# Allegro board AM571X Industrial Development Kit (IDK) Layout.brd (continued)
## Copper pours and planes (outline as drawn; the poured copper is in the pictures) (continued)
VDDR_VREF on L7_PWR2: 92.46,18.83 90.55,20.74 90.55,26.88 88.6,28.83 83.39,28.83 82.55,29.67 82.55,33.61 83.23,34.29 86.28,34.29 95.76,43.77 95.76,65.16 96.77,66.17 96.77,74.04 96.52,74.3 96.52,78.19 96.77,78.44 98.2,78.44 98.3,78.33 98.37,78.33 98.42,78.28 98.42,78.05 98.65,77.83 99.92,77.83 100.03,77.72 100.03,77.42 102.74,74.71 102.74,38.94 103.25,38.44 120.27,38.44 123.19,35.51 123.19,27.72 122.27,26.8 97.5,26.8 96.01,25.31 96.01,19.85 95,18.83
VDDR_VTT on TOP: 107.31,17.27 107.06,17.53 107.06,17.78 106.3,18.54 106.3,27.81 106.55,28.07 108.46,28.07 108.71,27.81 108.71,25.4 109.6,24.51 110.62,24.51 111.89,23.24 111.89,22.61 112.9,21.59 120.78,21.59 121.34,21.03 124.49,21.03 124.97,21.51 124.97,25.15 124.21,25.91 124.21,27.81 124.46,28.07 125.86,28.07 126.36,28.58 126.36,30.48 125.86,30.99 124.84,30.99 124.21,31.62 124.21,32.13 124.46,32.38 127.38,32.38 129.03,30.73 129.03,26.16 128.14,25.27 128.14,20.07 126.11,18.03 118.39,18.03 115.85,20.57 111.51,20.57 109.98,22.1 108.33,22.1 107.82,21.59 107.82,17.53 107.57,17.27
VDDR_VTT on BOTTOM: 107.31,23.62 108.46,22.48 110.62,22.48 111.38,21.72 111.38,19.3 111.76,18.92 127.13,18.92 128.35,20.14 128.35,29.69 128.07,29.97 124.41,29.97 124.21,29.77 124.21,22.48 123.32,21.59 114.05,21.59 113.54,22.1 113.54,22.61 108.71,27.43 108.71,28.19 108.58,28.32 108.58,30.61 108.46,30.73 107.57,30.73 107.31,30.48
VDDS_DDR on TOP (solid shape): 150.88,120.78 150.88,119.46 151.89,118.45 151.89,117.22 151.38,116.71 148.72,116.71 148.21,117.22 148.21,120.52 148.59,120.9 150.75,120.9
VDDS_DDR on TOP: 61.09,75.01 64.01,75.01 64.14,74.88 64.14,72.6 63.63,72.09 60.96,72.09 60.58,72.47 60.58,74.5
VDDS_DDR on TOP: 108.71,17.06 109.09,17.44 109.09,17.95 109.73,18.59 109.73,20.11 109.98,20.37 109.98,21.46 109.73,21.72 108.46,21.72 108.2,21.46 108.2,17.06
VDDS_DDR on BOTTOM: 83.95,36.32 85.85,36.32 86.11,36.07 86.11,35.69 85.85,35.43 83.95,35.43 83.69,35.69 83.69,36.07
VDDS_DDR on BOTTOM: 109.86,18.54 110.11,18.8 110.11,21.46 109.73,21.84 108.58,21.84 108.2,21.46 108.2,18.67 108.33,18.54
VDDS_DDR on BOTTOM: 86.74,33.43 87.1,33.78 87.38,33.78 87.63,33.53 87.63,32.26 87.25,31.88 84.33,31.88 83.69,32.51 83.69,33.3 83.82,33.43
VDDS_DDR on L6_PWR1: 151.26,119.21 144.4,119.21 141.99,116.79 133.22,116.79 132.33,115.91 132.33,114.76 126.24,108.67 126.24,105.49 125.09,104.35 121.41,104.35 120.27,103.21 120.27,89.74 120.35,89.67 120.35,77.42 119.93,77 119.93,48.63 113.66,42.37 67.18,42.37 65.15,44.4 65.15,73.84 63.91,75.09 51,75.09 49.78,73.87 49.78,26.37 51.64,24.52 65.46,24.52 71.58,18.39 82.55,18.39 84.86,16.08 97.66,16.08 99.95,18.37 111.76,18.37 112.78,17.35 113.41,17.35 114.43,18.37 164.21,18.37 168.4,22.56 168.4,86.36 166.73,88.03 143.07,88.03 140.59,90.51 140.59,101.94 152.02,113.37 152.02,118.45
(no net) on TOP: 127.06,136.13 129.96,136.13 130.51,135.58 130.51,133.91 130.35,133.74 126.88,133.74 126.67,133.96 126.67,135.74
(no net) on TOP: 140.21,120.73 141.22,120.73 141.61,120.35 141.61,118.95 141.48,118.83 140.59,118.83 139.95,119.46 139.95,120.48
(no net) on TOP: 145.03,128.61 145.03,130.13 147.7,132.8 147.7,134.19 147.83,134.32 150.88,134.32 151.13,134.07 151.13,132.03 149.61,130.51 149.1,130.51 147.96,129.37 147.96,129.11 146.49,127.65 144.71,127.65 144.65,127.72 144.65,128.25 144.65,128.26 144.65,128.31 144.76,128.41 144.84,128.41
(no net) on TOP: 138.59,131.47 138.21,131.1 138.05,131.1 138.05,131.25 137.94,131.36 137.94,133.32 138.18,133.56 138.43,133.56 138.59,133.4
(no net) on TOP: 143.26,113.62 145.59,113.62 145.8,113.41 145.8,108.46 146.56,107.7 146.56,105.16 145.8,104.39 144.15,104.39 143,105.54 143,113.37
(no net) on TOP: 151.38,116.71 148.72,116.71 148.21,117.22 148.21,120.52 148.59,120.9 150.75,120.9 150.88,120.78 150.88,119.46 151.89,118.45 151.89,117.22
(no net) on TOP: 133.86,113.62 136.53,113.62 136.91,113.24 136.91,110.83 136.65,110.57 133.86,110.57 133.48,110.95 133.48,113.24
(no net) on TOP: 133.6,116.42 133.57,116.4 133.57,115.43 133.99,115.02 136.91,115.02 138.03,116.14 138.03,120.37 138.05,120.39 138.05,120.6 137.82,120.83 137.67,120.68 137.67,120.6 137.54,120.48 137.54,119.97 136.65,119.08 134.11,119.08 133.6,118.56
(no net) on TOP: 139.32,119.97 139.45,119.97 141.1,118.32 141.86,118.32 142.11,118.06 142.11,115.52 141.73,115.14 138.68,115.14 138.43,115.4 138.43,118.83 139.19,119.59 139.19,119.84
(no net) on TOP: 127.47,132.59 130.3,132.59 130.3,132.54 133.99,128.86 134.9,128.86 134.87,128.84 136.22,128.84 136.33,128.73 136.33,128.22 136.23,128.13 136.11,128.13 135.98,128.26 135.72,128.26 135.67,128.21 135.59,128.13 134.24,128.13 134.04,128.34 132.22,128.34 130.18,130.38 127.25,130.38 127.12,130.51 127.12,132.24
(no net) on TOP: 127.67,127.21 129.92,127.21 130.68,127.97 133.22,127.97 133.6,127.59 133.6,126.18 133.22,125.8 132.06,125.8 130.79,124.53 127.24,124.53 127.19,124.58 127.19,126.73
(no net) on TOP: 138.81,113.62 141.1,113.62 142.09,112.63 142.09,111.05 141.61,110.57 138.56,110.57 138.18,110.95 138.18,112.98
(no net) on TOP: 134.14,141.3 138.98,141.3 139.55,140.73 139.55,136.09 137.54,134.08 137.54,131.11 136.94,130.51 136.78,130.51 136.53,130.76 135,130.76 134.75,130.51 134.36,130.51 134.04,130.82 134.04,135.53 133.55,136.02 133.55,137.02 132.89,137.68 132.89,140.06
(no net) on TOP: 133.22,125.4 132.06,125.4 130.73,124.08 127.32,124.08 127.32,124.07 127.27,124.07 127.08,123.89 127.08,121.66 127.38,121.37 131.95,121.37 133.27,122.68 133.27,125.36
(no net) on TOP: 138.83,133.32 138.94,133.43 138.94,133.81 139.07,133.94 139.32,133.94 139.47,133.78 139.47,131.27 139.32,131.12 139.32,130.31 139.24,130.23 139.04,130.23 138.83,130.44
(no net) on TOP: 150.88,124.92 150.37,125.43 145.92,125.43 145.29,124.8 145.29,124.03 145.92,123.4 147.57,123.4 149.1,121.87 150.5,121.87 150.88,122.26
(no net) on TOP: 142.49,120.1 143,119.59 144.78,119.59 146.69,117.68 146.69,115.65 146.3,115.27 143.13,115.27 142.75,115.65 142.75,118.06 141.99,118.83 141.99,119.97 142.11,120.1
(no net) on TOP: 145.03,127.21 146.69,127.21 148.34,128.86 148.34,129.11 148.59,129.37 150.88,129.37 151.26,128.99 151.26,126.07 151,125.81 145.16,125.81 144.7,126.28 144.7,126.87
(no net) on TOP: 144.78,130.89 144.78,131.78 145.03,132.03 145.03,134.45 145.29,134.7 146.69,134.7 146.94,134.45 146.94,132.67 145.03,130.76 144.91,130.76
(no net) on TOP: 137.29,121.24 137.29,120.1 136.65,119.46 135.26,119.46 135.13,119.59 135.13,119.97 136.02,120.86 136.02,121.11 136.27,121.37 137.16,121.37
(no net) on TOP: 141.35,135.84 141.99,135.84 142.11,135.72 142.11,133.18 141.61,132.67 140.84,132.67 140.21,133.3 140.21,134.7
(no net) on TOP: 149.53,88.14 157.35,88.14 159.82,85.67 159.82,83.95 159.44,83.57 159.18,83.57 157.4,81.79 156.26,81.79 154.86,80.4 149.91,80.4 148.89,81.41 148.89,87.51
(no net) on TOP: 151.77,126.95 151.77,134.07 152.27,134.57 153.54,134.57 154.56,133.56 154.56,127.46 153.92,126.83 151.89,126.83
(no net) on BOTTOM: 142.37,134.83 146.43,134.83 146.56,134.96 146.56,136.61 146.3,136.86 142.37,136.86 142.11,136.61 142.11,135.08
(no net) on BOTTOM: 39.5,92.84 39.5,98.17 39.75,98.42 41.02,98.42 42.29,97.16 43.69,97.16 44.45,97.92 48.39,97.92 49.28,97.03 49.28,95.63 48.26,94.61 43.05,94.61 41.4,92.96 41.4,91.57 40.64,90.8 38.48,90.8 38.23,91.06 38.23,91.57
(no net) on BOTTOM: 117.73,128.91 113.03,128.91 112.78,129.16 112.78,130.3 113.03,130.56 119.38,130.56 121.16,128.78 121.16,124.97 120.9,124.71 120.27,124.71 120.02,124.97 120.02,127.13 119.51,127.64 119,127.64
(no net) on BOTTOM: 137.03,121.62 137.03,120.1 136.78,119.84 136.78,117.94 137.03,117.68 142.49,117.68 143,118.19 143,121.24 142.88,121.37 138.68,121.37 138.18,121.87 137.29,121.87
(no net) on BOTTOM: 145.01,129.65 146.63,129.65 147.07,129.21 147.07,128.27 146.79,128 145.39,128 144.88,128.5 144.88,129.52
(no net) on BOTTOM: 148.34,134.07 150.24,134.07 150.5,133.81 150.5,127.46 150.24,127.21 148.34,127.21 148.08,127.46 148.08,133.81
(no net) on BOTTOM: 127.13,134.07 127.13,135.84 127.51,136.23 130.18,136.23 130.68,135.72 130.68,134.19 130.35,133.86 127.33,133.86
(no net) on BOTTOM: 139.34,125.7 139.57,125.93 140.72,125.93 140.97,125.68 140.97,124.41 140.84,124.29 138.18,124.29 137.92,124.03 137.92,123.14 136.27,123.14 136.14,123.27 136.14,125.3 136.54,125.7
(no net) on BOTTOM: 36.2,93.09 38.1,93.09 38.23,92.96 38.23,92.33 37.97,92.08 37.97,91.06 37.72,90.8 36.96,90.8 34.42,93.34 34.42,96.27 34.67,96.52 35.18,96.52 35.31,96.39 35.31,93.98
(no net) on BOTTOM: 154.74,106.9 154.23,106.9 153.32,107.81 151.48,107.81 151,108.29 149.48,108.29 149.23,108.03 149.23,106.51 149.47,106.27 154.74,106.27
(no net) on BOTTOM: 146.39,125.81 148.84,125.81 149.1,125.56 149.1,122.89 147.7,121.49 147.7,119.84 147.57,119.72 146.6,119.72 144.78,121.54 144.78,122.05 145.03,122.3 145.03,124.46
(no net) on BOTTOM: 151.64,133.81 152.4,134.57 154.18,134.57 154.69,134.07 154.69,126.95 154.31,126.57 152.02,126.57 151.64,126.95
(no net) on BOTTOM: 159.05,112.87 159.05,110.35 155.99,107.28 155.63,107.28 155.63,107.37 155.91,107.65 155.91,108.69 155.63,108.97 155.63,112.87 156.13,113.38 158.55,113.38
(no net) on BOTTOM: 34.04,96.9 37.34,96.9 38.23,97.79 38.23,98.42 37.97,98.68 34.04,98.68 33.91,98.55 33.91,97.03
(no net) on BOTTOM: 133.22,127.34 133.22,130.38 132.84,130.76 131.44,130.76 131.19,131.02 131.19,132.54 131.44,132.8 135.26,132.8 135.76,132.29 135.76,130.64 135.13,130 135.13,128.86 135.64,128.35 135.76,128.35 136.14,127.97 136.14,126.83 135.64,126.32 134.87,126.32 134.11,125.56 133.1,125.56 132.97,125.68 132.97,127.08
(no net) on BOTTOM: 158.8,83.13 164.01,83.13 164.39,82.75 164.39,81.48 164.13,81.22 159.18,81.22 158.55,81.86 158.55,82.87
(no net) on BOTTOM: 139.32,134.96 138.05,134.96 137.16,135.84 137.16,136.73 137.41,136.99 139.07,136.99 139.45,136.61 139.45,135.08
(no net) on BOTTOM: 153.45,105.9 150.16,105.9 149.91,105.65 149.91,103.58 150.11,103.38 153.1,103.38 153.72,104 153.72,105.63
(no net) on BOTTOM: 130.99,130.05 132.13,130.05 132.64,129.54 132.64,128.38 132.33,128.07 131.17,128.07 130.71,128.53 130.71,129.77
(no net) on BOTTOM: 141.35,127.21 143.64,127.21 143.76,127.08 143.76,126.07 143.64,125.94 141.35,125.94 141.1,126.19 141.1,126.95
(no net) on BOTTOM: 117.47,125.73 117.47,127.51 117.6,127.64 118.24,127.64 118.49,127.38 119.51,127.38 119.76,127.13 119.76,124.21 118.49,122.94 114.43,122.94 114.05,123.32 114.05,124.59 114.17,124.71 116.46,124.71
(no net) on BOTTOM: 145.36,132.11 144.68,131.42 141.27,131.42 141.1,131.6 141.1,132.16 141.73,132.8 141.73,133.86 142.06,134.19 145.29,134.19 145.36,134.12
(no net) on BOTTOM: 4.32,47.2 5.03,46.49 5.03,43.34 4.8,43.11 3.2,43.11 2.54,43.77 1.43,43.77 1.43,46.97 1.65,47.2
(no net) on BOTTOM: 4.75,39.12 4.95,38.92 4.95,35.41 4.55,35.01 2.03,35.01 1.3,35.74 1.3,38.08 2.16,38.08 3.2,39.12
(no net) on BOTTOM: 35.81,96.52 38.23,96.52 38.35,96.39 38.35,94.36 38.1,94.11 35.81,94.11 35.64,94.28 35.64,96.34
(no net) on BOTTOM: 155.02,107.01 155.02,107.25 154.67,107.6 154.67,108.49 153.47,109.7 153.47,112.62 152.83,113.25 151.43,113.25 151.05,112.87 151.05,109.95 152.83,108.17 153.85,108.17 155.01,107.01
(no net) on BOTTOM: 113.66,123.7 113.66,126.75 112.14,128.27 112.14,131.7 111.76,132.08 109.98,132.08 109.73,131.83 109.73,128.14 111.89,125.98 111.89,123.7 112.27,123.32 113.28,123.32
(no net) on BOTTOM: 133.48,113.37 136.78,113.37 137.03,113.11 137.03,110.83 136.78,110.57 133.99,110.57 133.35,111.21 133.35,113.24
(no net) on BOTTOM: 158.93,81.16 164.13,81.16 164.52,80.78 164.52,79.51 164.21,79.2 159.36,79.2 158.67,79.89 158.67,80.9
(no net) on BOTTOM: 130.89,126.78 132.38,126.78 132.46,126.7 132.46,125.05 132.21,124.8 131.32,124.8 130.68,125.43 130.68,126.57
(no net) on BOTTOM: 127.38,122.51 127.38,126.32 127.51,126.45 130.05,126.45 130.56,125.94 130.56,122.64 130.3,122.38 127.51,122.38
(no net) on BOTTOM: 167.13,43.39 167.13,45.8 167.39,46.06 168.02,46.06 168.34,45.74 168.34,44.98 168.53,44.79 168.53,43.52 168.28,43.26 167.26,43.26
(no net) on BOTTOM: 125.55,115.17 125.3,115.42 125.3,117.86 125.73,118.29 129.01,118.29 129.29,118.01 129.29,115.47 128.98,115.17
(no net) on BOTTOM: 173.06,94.19 170.39,94.19 170.13,93.93 170.13,91.14 170.52,90.76 174.45,90.76 174.83,91.14 174.83,92.54 174.71,92.66 173.82,92.66 173.31,93.17 173.31,93.93
(no net) on BOTTOM: 127.25,130 130.3,130 130.56,129.75 130.56,127.97 130.3,127.72 127.51,127.72 127.13,128.1 127.13,129.88
(no net) on BOTTOM: 114.05,125.22 114.05,127.64 114.17,127.76 116.2,127.76 116.46,127.51 116.46,125.22 116.28,125.04 114.22,125.04
(no net) on BOTTOM: 127.25,121.09 130.3,121.09 130.56,120.83 130.56,119.06 130.3,118.8 127.51,118.8 127.13,119.18 127.13,120.96
(no net) on BOTTOM: 133.22,125.3 135,125.3 135.26,125.05 135.26,123.02 135.13,122.89 132.08,122.89 131.93,123.04 131.93,123.37 132.23,123.68 132.23,124.31
(no net) on BOTTOM: 141.1,129.11 143.74,129.11 144.91,127.94 144.91,127.53 144.7,127.32 144.03,127.32 143.64,127.72 141.35,127.72 140.97,127.34 140.97,126.45 140.87,126.35 139.8,126.35 139.7,126.45 139.7,127.72
(no net) on BOTTOM: 131.32,135.59 131.32,133.56 131.57,133.3 135.76,133.3 136.14,133.69 136.14,135.97 135.89,136.23 131.95,136.23
(no net) on BOTTOM: 138.94,133.18 138.94,131.65 139.07,131.53 139.95,131.53 140.21,131.78 140.21,134.19 139.83,134.57 138.56,134.57 138.3,134.32 138.3,133.81
(no net) on BOTTOM: 127.38,132.16 130.56,132.16 130.81,131.91 130.81,131.27 130.43,130.89 127.38,130.89 127.25,131.02 127.25,132.03
(no net) on L3_SIG1: 27.2,83.16 34.11,83.16 35.64,81.64 35.64,78.47 34.92,77.75 24.92,77.75 24.21,78.47 24.21,80.17
(no net) on L3_SIG1: 26.54,100.54 27.86,100.54 30.91,97.49 33.27,97.49 33.91,96.86 33.91,96.22 33.27,95.59 24.54,95.59 24.21,95.92 24.21,98.2
(no net) on L3_SIG1: 26.03,58.76 32.29,58.76 35.64,55.41 35.64,53.88 35.26,53.5 34.37,53.5 33.6,54.26 24.59,54.26 24.21,54.64 24.21,56.93
(no net) on L10_SIG4: 36.96,98.3 37.59,97.66 37.59,97.03 37.08,96.52 34.29,96.52 33.66,97.16 33.66,97.79 34.16,98.3
AM57XX_USB1_DRVVBUS on L9_SIG3: 93.7,87.33 94.74,87.33 95.76,86.31 95.76,84.27 94.82,83.33 91.56,83.33 86.5,88.39 86.5,88.4 85.72,89.18 85.72,90.63 86.02,90.93 87.41,90.93 88.55,89.8 88.55,87.97 90.48,86.03 92.41,86.03 92.41,86.04
BKLT_L on TOP: 70.86,144.25 70.36,144.75 70.36,146.41 70.74,146.79 80.13,146.79 80.64,146.28 80.64,144.63 80.26,144.25
BKLT_L on BOTTOM: 73.13,146.61 73.13,145.6 72.24,145.6 71.48,144.84 70.59,144.84 70.36,145.07 70.36,146.38 70.59,146.61
BKLT_SW on TOP: 70.74,140.94 70.36,141.33 70.36,143.48 70.74,143.87 80.26,143.87 80.64,143.48 80.64,141.58 80.01,140.94
BKLT_SW on BOTTOM: 73.15,143.57 73.15,142.7 72.27,142.7 71.86,142.3 70.34,142.3 70.09,142.55 70.09,143.31 70.34,143.57
ETH1_LDO_O on TOP: 64.64,111.08 65.53,111.08 65.79,110.83 65.79,107.78 65.66,107.65 64.52,107.65 64.39,107.78 64.39,110.83
FTDI_VPHY on BOTTOM (solid shape): 164.39,82.75 164.39,81.57 164.36,81.52 164.3,81.53 164.29,81.54 160.33,81.54 160.32,81.57 159.94,81.82 159.57,81.57 159.56,81.54 158.86,81.54 158.55,81.86 158.55,82.87 158.8,83.13 164.01,83.13
FTDI_VPLL on BOTTOM (solid shape): 159.63,81.16 159.94,81 160.26,81.16 164.13,81.16 164.52,80.78 164.52,79.51 164.21,79.2 161.34,79.2 161.25,79.31 161.13,79.38 161.13,79.51 160.62,79.51 160.62,79.38 160.5,79.31 160.41,79.2 159.36,79.2 158.67,79.89 158.67,80.9 158.93,81.16
VADD33_PRU1ETH0 on BOTTOM: 21.97,121.87 21.97,123.14 22.48,123.65 23.37,123.65 23.62,123.4 23.62,123.02 23.37,122.76 23.11,122.76 22.23,121.87
VADD33_PRU1ETH1 on TOP: 26.11,100.54 26.54,100.54 27.03,100.06 27.03,98.63 26.8,98.4 26.39,98.4 26.16,98.63 26.16,99.78 25.88,100.06 25.88,100.31
VADD33_PRU1ETH1 on BOTTOM: 26.37,101.43 29.79,101.43 29.92,101.3 29.92,100.16 29.67,99.9 27.53,99.9 27.03,99.4 27.03,98.63 26.77,98.38 26.37,98.38 25.98,98.76 25.98,101.05
VADD33_PRU2ETH0 on TOP: 26.06,82.78 26.54,82.78 26.97,82.35 26.97,80.9 26.8,80.73 26.31,80.73 25.98,81.06 25.98,82.4 26.06,82.48
VADD33_PRU2ETH0 on BOTTOM: 26.37,83.73 29.79,83.73 29.92,83.6 29.92,82.46 29.67,82.2 29.03,82.2 27.51,80.68 26.37,80.68 25.98,81.06 25.98,83.35
VADD33_PRU2ETH1 on TOP: 26.37,57.41 27.51,57.41 27.74,57.18 27.74,56.8 27.53,56.6 27.1,56.6 26.97,56.47 26.97,56.11 26.72,55.86 26.31,55.86 26.16,56.01 26.16,57.18 26.37,57.38
VADD33_PRU2ETH1 on BOTTOM: 26.37,58.96 29.79,58.96 29.92,58.84 29.92,57.69 29.67,57.44 29.03,57.44 29,57.41 28.4,57.41 27.56,56.57 27.3,56.57 27,56.27 27,55.91 26.37,55.91 25.98,56.3 25.98,58.58
VAM572X_DDR1 on TOP: 95.77,74.26 96.51,74.26 96.65,74.12 96.65,72.69 96.51,72.56 95.69,72.56 95.58,72.67 95.58,74.07
VAM572X_DDR1 on TOP: 67.06,72.47 69.22,72.47 69.72,71.96 69.72,71.2 69.22,70.69 67.06,70.69 66.55,71.2 66.55,71.96
VAM572X_DDR1 on TOP: 95.94,76.71 97.18,76.71 97.33,76.56 97.33,75.26 97.08,75.01 95,75.01 94.82,75.18 94.82,75.59
VAM572X_DDR1 on TOP: 100.6,74.28 101.38,74.28 101.57,74.09 101.57,72.75 101.41,72.58 100.52,72.58 100.33,72.77 100.33,74.02
VAM572X_DDR1 on TOP: 61.09,78.69 63.63,78.69 64.14,78.19 64.14,75.9 64.01,75.77 61.09,75.77 60.71,76.15 60.71,78.31
VAM572X_DDR1 on BOTTOM: 66.29,72.47 71.37,72.47 72.01,71.84 72.01,66.88 71.5,66.38 67.18,66.38 65.79,67.77 65.79,71.96
VAM572X_DDR1 on BOTTOM: 93.85,75.92 95.66,75.92 96.14,75.44 96.14,73.79 97.92,72.01 97.92,70.74 97.79,70.61 95.89,70.61 95.76,70.74 95.76,71.58 95.59,71.75 94.61,71.75 94.36,71.5 94.36,70.23 94.16,70.03 91.82,70.03 90.17,71.68 90.17,72.26 90.53,72.62 91.16,72.62 91.54,72.24 91.54,71.5 91.82,71.22 92.18,71.22 93.73,72.77 93.73,75.79
VAM572X_DDR1 on L3_SIG1: 95.38,76.28 96.65,76.28 96.85,76.07 96.85,75.64 96.65,75.44 96.39,75.44 96.01,75.06 94.54,75.06 94.54,75.44
VAM572X_DDR1 on L3_SIG1: 101.02,73.55 101.02,72.36 100.72,72.07 100.29,72.07 99.92,72.44 99.92,73.71 100.13,73.91 100.65,73.91
VAM572X_DDR1 on L6_PWR1: 67.82,42.63 65.79,44.66 65.79,74.12 64.14,75.77 60.2,75.77 59.44,76.54 59.44,82.25 60.83,83.65 94.23,83.65 94.46,83.42 100.84,83.42 101.09,83.16 101.09,79.5 100.18,78.59 100.18,76.73 100.71,76.2 116.08,76.2 117.22,77.34 117.22,101.22 120.78,104.77 125.35,104.77 126.24,105.66 126.24,108.97 132.46,115.19 132.46,116.2 133.73,117.47 141.99,117.47 143.89,119.38 143.89,120.4 144.15,120.65 145.92,120.65 146.3,120.27 146.3,119 141.99,114.68 135.76,114.68 129.16,108.08 129.16,104.65 126.11,101.6 123.95,101.6 123.19,100.84 123.19,52.28 113.54,42.63
VAM572X_DDR1 on L10_SIG4: 96.52,71.46 96.14,71.07 95.76,71.07 95.63,71.2 95.63,71.46 94.61,72.47 94.61,73.99 93.8,74.8 93.8,75.16 93.93,75.29 94.46,75.29 95.28,76.1 95.99,76.1 95.99,75.64 96.14,75.49 96.14,75.23 95.96,75.06 95.96,74.85 96.52,74.3
VCAN1 on TOP: 165.96,29.6 167.94,29.6 168.33,29.21 168.33,26.04 165.56,23.27 157.53,23.27 155.63,21.37 155.63,13.92 154.53,12.83 151.54,12.83 151,13.37 148.54,13.37 148.08,13.82 148.08,19.89 155.07,26.88 164.54,26.88 165.35,27.69 165.35,28.99
VETH0_AVDDH on BOTTOM: 48.13,116.92 48.89,116.16 48.89,113.75 48.51,113.37 47.5,113.37 46.86,114 46.86,117.94 46.48,118.32 46.48,123.91 46.74,124.16 47.88,124.16 48.13,123.91
VETH0_AVDDH on L4_SIG2: 30.48,127.34 44.96,127.34 47.75,124.54 47.75,122.51 46.61,121.37 40.26,121.37 37.08,124.54 30.61,124.54 29.97,125.18 29.97,126.83
VETH0_AVDDL on BOTTOM: 43.69,123.65 43.69,124.8 43.43,125.05 38.84,125.05 38.33,125.56 33.66,125.56 33.15,125.05 33.15,124.41 33.66,123.91 37.87,123.91 38.25,123.53 43.56,123.53
VETH0_AVDDL_PLL on BOTTOM: 38.94,123.02 43.05,123.02 43.81,122.26 43.81,121.24 43.56,120.99 38.99,120.99 38.73,121.24 38.73,122.81
VETH0_AVDDL_PMOS on BOTTOM: 43.31,109.17 43.31,110.32 44.7,111.71 44.7,117.56 44.2,118.06 44.2,125.05 43.81,125.43 43.81,126.95 44.32,127.46 46.1,127.46 46.48,127.08 46.48,125.56 45.97,125.05 45.97,118.06 46.61,117.43 46.61,112.22 47.62,111.21 47.62,109.05 47.24,108.67 43.81,108.67
VETH0_DVDDH on BOTTOM: 28.45,118.19 29.08,118.19 30.23,117.05 30.43,117.05 30.86,116.62 30.86,116.16 30.35,115.65 28.45,115.65 27.69,116.41 27.69,117.43
VETH0_DVDDH on L4_SIG2: 29.34,122.89 29.97,122.89 32.38,120.48 42.42,120.48 43.18,119.72 43.18,111.33 43.14,111.29 43.14,108.6 42.07,107.52 38.32,107.52 38.14,107.7 38.14,109.66 39.88,111.4 39.88,112.86 39.24,113.49 30.86,113.49 28.45,115.91 27.43,115.91 27.05,116.29 27.05,120.6
VETH0_DVDDL on BOTTOM: 43.56,119.59 43.81,119.33 43.81,118.45 43.56,118.19 42.55,118.19 41.27,116.92 38.61,116.92 37.41,115.73 32.21,115.73 29.59,118.34 29.59,122.51 30.48,123.4 31.62,123.4 32.77,122.26 32.77,121.49 34.67,119.59
VETH1_AVDDH on TOP: 72.9,106.25 72.39,105.75 69.34,105.75 68.96,106.13 68.96,110.19 70.61,111.84 70.61,116.67 69.47,117.81 69.47,127.59 68.58,128.48 64.64,128.48 64.01,129.11 64.01,130.51 64.26,130.76 70.48,130.76 72.9,128.35
VETH1_AVDDH on BOTTOM: 50.67,127.08 52.45,127.08 53.09,126.45 58.06,126.45 62.38,130.76 66.67,130.76 67.06,130.38 67.06,128.86 66.67,128.48 62.03,128.48 60.2,126.65 60.2,125.53 60.1,125.43 59.21,125.43 59.08,125.56 54.81,125.56 53.8,124.54 50.67,124.54 50.29,124.92 50.29,126.7
VETH1_AVDDL on TOP: 65.53,123.27 65.28,123.02 64.14,123.02 63.63,123.53 63.63,124.8 63.88,125.05 65.41,125.05 65.53,124.92
VETH1_AVDDL on BOTTOM: 65.66,124.54 65.15,125.05 59.05,125.05 58.55,125.56 55.37,125.56 54.86,125.05 54.86,124.41 55.68,123.6 64.31,123.6 64.9,123.02 65.41,123.02 65.66,123.27
VETH1_AVDDL_PLL on TOP: 64.39,122.64 65.28,122.64 65.53,122.38 65.53,120.86 65.28,120.6 64.14,120.6 63.88,120.86 63.88,121.24 64.14,121.49 64.14,122.38
VETH1_AVDDL_PLL on BOTTOM: 60.71,123.27 64.52,123.27 65.53,122.26 65.53,120.99 65.28,120.73 64.01,120.73 63.75,120.99 60.58,120.99 60.32,121.24 60.32,122.89
VETH1_AVDDL_PMOS on TOP: 65.91,111.46 65.91,128.22 66.42,128.73 67.69,128.73 68.77,127.65 68.77,116.98 69.47,116.29 69.47,112.6 68.2,111.33 68.2,107.78 67.82,107.4 66.8,107.4 66.55,107.65 66.55,110.83
VETH1_DVDDH on BOTTOM: 50.04,115.02 51.31,115.02 51.43,114.89 51.43,112.6 51.31,112.48 49.4,112.48 49.15,112.73 49.15,114.51 49.53,114.89 49.91,114.89
VETH1_DVDDH on L4_SIG2: 52.07,122.89 61.59,122.89 64.26,120.22 64.26,111.08 61.93,108.74 49.76,108.74 48.64,109.86 48.64,119.59 47.88,120.35 47.88,121.62 49.78,123.53 51.43,123.53
VETH1_DVDDL on BOTTOM: 58.55,118.19 59.44,118.19 60.83,119.59 64.01,119.59 64.01,119.84 64.52,120.35 65.28,120.35 65.53,120.1 65.53,117.81 64.64,116.92 60.32,116.92 58.93,115.52 51.43,115.52 51.31,115.65 51.31,122.51 52.2,123.4 53.34,123.4 54.48,122.26 54.48,119.97 55.5,118.95 57.78,118.95
VLDO2_OUT on TOP (solid shape): 139.47,133.78 139.47,131.67 139.46,131.64 139.43,131.62 139.13,131.4 139.23,131.04 139.24,131.03 139.24,130.96 139.23,130.95 139.14,130.74 139.23,130.53 139.26,130.45 139.23,130.38 139.06,130.21 138.83,130.44 138.83,130.5 138.85,130.51 138.95,130.75 138.83,130.98 138.83,131.18 138.97,131.32 138.97,133.56 138.94,133.59 138.94,133.81 139.07,133.94 139.32,133.94
VLDO2_OUT on BOTTOM (solid shape): 140.02,134.38 140.02,134.36 140.09,134.18 140.21,134.02 140.21,131.78 139.95,131.53 139.07,131.53 138.94,131.65 138.94,133.18 138.88,133.24 138.87,133.26 138.7,133.64 138.3,133.8 138.3,134.32 138.56,134.57 139.07,134.57 139.83,134.57
VLED+ on BOTTOM: 73.41,136.86 70.36,136.86 69.98,137.24 69.98,138.64 70.23,138.89 70.23,141.69 70.48,141.94 72.36,141.94 73.28,142.32 73.41,142.45 73.66,142.45 73.79,142.32 73.79,137.24
VLED+ on L9_SIG3: 71.25,141.81 75.36,141.81 82.55,134.62 82.55,128.48 81.91,127.84 80.01,127.84 70.61,137.24 70.61,141.18
VLED- on BOTTOM: 76.07,146.64 76.58,147.15 81.41,147.15 82.04,146.51 82.04,145.12 81.61,144.68 78.18,144.68 77.5,145.37 75.79,145.37 75.54,145.62 75.06,145.62 74.93,145.75 74.93,146.51 75.06,146.64
VLED- on BOTTOM: 82.42,124.8 81.79,125.43 81.79,127.08 82.04,127.34 82.68,127.34 82.8,127.46 84.96,127.46 85.09,127.34 85.09,125.05 84.84,124.8
VLED- on L9_SIG3: 77.85,146.51 78.87,147.53 81.03,147.53 88.77,139.78 88.77,126.45 86.36,124.03 81.91,124.03 81.28,124.67 81.28,126.7 81.66,127.08 81.91,127.08 83.31,128.48 83.31,135.26 77.85,140.72
VMAIN on TOP (solid shape): 141.54,120.41 141.54,118.95 141.54,118.89 141.48,118.83 140.59,118.83 140.01,119.4 140.02,119.46 140.02,120.54 140.21,120.73 141.22,120.73
VMAIN on TOP (solid shape): 137.28,121.24 137.28,121.18 137.27,121.14 137.27,120.08 136.65,119.46 135.26,119.46 135.13,119.59 135.13,119.97 136.02,120.86 136.02,121.11 136.27,121.37 137.16,121.37
VMAIN on BOTTOM (solid shape): 147.07,129.21 147.07,128.27 147,128.21 145.18,128.21 144.88,128.51 144.88,129.52 145.01,129.65 146.63,129.65
VMAIN on BOTTOM (solid shape): 151.48,107.81 153.32,107.81 154.23,106.9 154.74,106.9 154.74,106.27 153.34,106.27 153.34,106.27 152.83,106.27 152.83,106.27 149.47,106.27 149.23,106.51 149.23,108.03 149.48,108.29 151,108.29
VMAIN on BOTTOM (solid shape): 145.36,134.12 145.36,132.11 144.68,131.42 141.84,131.42 141.73,131.44 141.63,131.42 141.27,131.42 141.1,131.6 141.1,132.16 141.73,132.8 141.73,133.86 142.06,134.19 145.29,134.19
VMAIN on BOTTOM (solid shape): 135.76,132.29 135.76,130.64 135.13,130 135.13,128.86 135.64,128.35 135.76,128.35 136.14,127.97 136.14,126.84 136.1,126.81 136.07,126.78 135.61,126.32 134.87,126.32 134.42,125.87 132.97,125.87 132.97,127.08 133.22,127.34 133.22,130.38 132.84,130.76 131.44,130.76 131.19,131.02 131.19,132.54 131.44,132.8 135.26,132.8
VMAIN on BOTTOM (solid shape): 149.1,125.56 149.1,122.89 147.7,121.49 147.7,119.84 147.57,119.72 146.6,119.72 146.2,120.12 146.2,120.14 146.08,120.43 145.79,120.55 145.77,120.55 144.78,121.54 144.78,122.05 145.03,122.3 145.03,123.18 145.08,123.31 145.1,123.44 145.1,124.52 145.48,124.9 145.67,124.9 146.12,125.12 146.22,125.61 146.22,125.64 146.39,125.81 148.84,125.81
VMAIN on BOTTOM (solid shape): 138.68,121.37 139.78,121.37 139.85,121.34 139.88,121.27 140.21,120.95 140.54,121.27 140.57,121.34 140.64,121.37 141.56,121.37 141.57,121.36 141.73,121.33 141.9,121.36 141.91,121.37 142.57,121.37 142.67,121.34 142.76,121.33 142.91,121.33 143,121.24 143,118.19 142.88,118.07 142.86,118.07 142.65,118.01 142.49,117.87 142.45,117.82 142.39,117.88 141.87,118.03 141.45,117.68 137.03,117.68 136.78,117.94 136.78,119.84 137.03,120.1 137.03,121.62 137.29,121.87 138.18,121.87
VMAIN on TOP: 185.7,119.97 176.29,119.97 172.36,116.04 172.36,112.35 166.65,106.63 166.65,102.72 166.12,102.19 162.59,102.19 162.08,102.7 162.08,111.99 161.04,113.03 158.62,113.03 158.37,113.28 158.37,113.79 158.17,114 155.63,114 155.58,114.05 155.58,114.81 155.78,115.02 168.68,115.02 169.95,116.29 169.95,125.68 170.21,125.94 177.7,125.94 178.21,126.45 185.8,126.45 186.94,125.3 186.94,121.21
VMAIN on TOP: 158.12,123.91 158.75,123.91 159,124.16 159,128.48 158.37,129.11 158.37,133.94 158.24,134.07 156.08,134.07 155.32,133.3 155.32,128.86 156.08,128.1 157.48,128.1 157.86,127.72 157.86,124.16
VMAIN on TOP: 75.69,130.76 74.3,129.37 74.3,115.52 76.71,113.11 76.71,110.32 75.82,109.43 75.82,107.9 76.33,107.4 79.5,107.4 81.91,109.81 81.91,113.87 79.25,116.54 79.25,128.35 79.63,128.73 79.63,130.26 79.12,130.76
VMAIN on TOP: 157.23,139.57 157.48,139.32 157.48,137.29 156.72,136.53 154.05,136.53 153.8,136.78 153.8,138.56 154.05,138.81 155.58,138.81 156.34,139.57
VMAIN on BOTTOM: 73.51,145.72 73.51,146.87 73.13,147.25 72.75,147.25 72.63,147.38 72.63,148.52 72.5,148.65 72.5,148.67 72.37,148.8 70.99,148.8 70.1,149.69 70.1,150.58 70.42,150.89 73.64,150.89 74.04,150.5 74.04,147.32 73.77,147.05 73.77,145.72
VMAIN on BOTTOM: 155.83,129.88 158.5,129.88 159.64,128.73 159.64,126.07 159.39,125.81 158.37,125.81 158.12,126.07 158.12,127.59 157.73,127.97 156.21,127.97 155.58,128.61 155.58,129.62
VMAIN on BOTTOM: 166.14,112.98 169.32,112.98 171.09,114.76 171.09,118.83 173.38,121.11 186.31,121.11 186.94,121.75 186.94,125.81 186.44,126.32 167.28,126.32 166.65,125.68 166.65,120.48 165.56,119.38 165.56,113.57
VMAIN on BOTTOM: 70.74,111.21 72.26,111.21 72.52,110.95 72.52,109.17 79.12,109.17 79.38,108.92 79.38,108.16 78.49,107.27 70.87,107.27 70.74,107.4
VMAIN on L3_SIG1: 142.68,125.74 142.68,124.83 143.04,124.46 147.45,124.46 147.7,124.71 147.7,126.07 147.45,126.32 145.16,126.32 144.78,125.94 142.88,125.94
VMAIN on L3_SIG1: 141.35,128.78 141.35,130.18 142.18,131 142.31,131 142.39,131.09 142.39,132.13 142.09,132.43 140.18,132.43 139.65,131.9 139.65,130.96 139.51,130.81 136.78,130.81 136.27,131.32 136.27,132.08 135.43,132.92 133.73,132.92 133.6,132.8 133.6,127.25 134.24,126.62 139.19,126.62
VMAIN on L3_SIG1: 144.53,122.76 147.7,122.76 148.08,122.38 148.08,122 147.32,121.24 145.03,121.24 144.27,122 144.27,122.51
VMAIN on L3_SIG1: 132.72,124.92 135.64,124.92 136.14,124.41 136.14,123.78 132.59,123.78 132.46,123.91 132.46,124.67
VMAIN on L3_SIG1: 135,119.08 135,119.97 136.4,121.37 141.1,121.37 141.86,120.6 141.86,118.7 141.73,118.57 135.51,118.57
VMAIN on L3_SIG1: 142.88,128.99 145.16,128.99 145.8,129.62 146.81,129.62 147.07,129.37 147.07,128.35 146.94,128.22 143,128.22 142.75,128.48 142.75,128.86
VMAIN on L6_PWR1: 168.66,132.42 168.78,132.54 168.78,115.19 169.42,114.55 169.42,112.9 168.78,112.27 168.78,93.22 167.89,92.33 167.89,92.08 168.78,91.19 168.78,90.38 167.26,88.85 142.11,88.85 141.22,89.74 141.22,101.73 152.53,113.03 152.53,118.83 151.51,119.84 144.15,119.84 141.73,117.43 133.48,117.43 132.33,118.57 132.33,126.57 134.87,129.11 136.53,129.11 138.43,131.02 138.81,131.02 139.45,131.65 140.59,131.65 141.22,132.29 142.88,132.29 144.4,130.76 146.43,130.76 147.57,131.91 147.57,137.88 145.03,140.42 126.36,140.42 116.84,130.89 116.84,130.76 84.96,130.76 82.68,128.48 82.68,126.57 82.42,126.32 73.79,126.32 70.48,129.62 70.48,134.7 70.61,134.83 70.61,149.8 71.31,150.5 83.75,150.5 84.35,149.9 96.53,149.9 97.13,150.5 168.42,150.5 168.66,150.26
VMAIN on L10_SIG4: 133.73,128.48 135.89,128.48 136.27,128.1 136.27,127.08 134.11,124.92 134.11,124.03 133.86,123.78 132.59,123.78 132.33,124.03 132.33,127.08
VMAIN on L10_SIG4: 144.65,129.62 144.78,129.75 147.19,129.75 147.32,129.62 147.32,128.61 147.07,128.35 144.91,128.35 144.65,128.61
VMAIN on L10_SIG4: 145.42,125.98 147.57,125.98 148.08,125.48 148.08,121.49 147.7,121.11 145.16,121.11 144.65,121.62 144.65,122.26 144.91,122.51 144.91,125.48
VMAIN on L10_SIG4: 132.74,132.57 133.1,132.92 135.26,132.92 136.14,132.03 136.14,131.53 135.51,130.89 133.05,130.89 132.74,131.2
VMAIN on L10_SIG4: 136.27,121.49 140.72,121.49 141.61,120.6 141.61,118.83 141.48,118.7 136.02,118.7 135.64,119.08 135.64,120.86
VMAIN on L10_SIG4: 138.68,130.76 138.81,130.76 139.95,131.91 139.95,132.67 140.46,133.18 143.38,133.18 143.64,132.92 143.64,131.65 143,131.02 140.72,131.02 139.57,129.88 138.81,129.88 138.56,130.13 138.56,130.64
VPROFI on TOP: 114.55,4.32 114.94,3.94 115.95,3.94 116.2,4.19 118.75,4.19 119,3.94 119,2.41 118.75,2.16 112.14,2.16 111.89,2.41 111.89,3.94 112.27,4.32
VPROFI on BOTTOM: 99.44,10.24 102.79,10.24 103.25,9.78 103.25,6.22 102.87,5.84 99.27,5.84 98.81,6.3 98.81,9.61
VPROFI on L3_SIG1: 98.68,6.83 99.52,7.67 108.92,7.67 112.37,4.22 114,4.22 114.45,3.76 114.45,1.88 113.84,1.27 110.34,1.27 109.52,2.08 109.52,2.97 107.49,5 105.23,5 104.8,4.57 99.06,4.57 98.68,4.95
VPROFI_SRC on BOTTOM: 99.44,12.7 108.46,12.7 113.41,7.75 117.22,7.75 117.47,8 117.47,9.53 117.98,10.03 119.13,10.03 119.38,9.78 119.38,6.48 119.13,6.22 117.47,6.22 116.33,5.08 111.38,5.08 105.66,10.79 99.31,10.79 99.19,10.92 99.19,12.45
VPROFI_TRANSA on BOTTOM: 117.35,13.46 121.54,13.46 123.06,11.94 123.06,10.54 122.94,10.41 121.54,10.41 119.76,12.19 117.22,12.19 117.09,12.32 117.09,13.21
VPROFI_TRANSB on BOTTOM: 117.86,4.06 120.14,4.06 121.28,5.21 121.28,5.84 121.54,6.1 123.32,6.1 123.57,5.84 123.57,3.94 121.92,2.29 117.86,2.29 117.47,2.67 117.47,3.68
VPWRIN_JCK on TOP: 176.68,103.01 176.68,105.87 173.13,109.43 173.13,113.49 174.27,114.64 176.94,114.64 178.97,112.6 178.97,110.19 180.62,108.54 183.16,108.54 184.81,110.19 184.81,111.33 185.57,112.1 187.99,112.1 188.75,111.33 188.75,104.48 187.03,102.76 176.94,102.76
VPWRIN_JCK on BOTTOM: 171.48,109.68 164.36,109.68 163.86,110.19 163.86,112.1 164.24,112.48 170.59,112.48 173.51,115.4 177.19,115.4 178.97,113.62 178.97,110.19 180.62,108.54 183.16,108.54 184.81,110.19 184.81,111.71 185.57,112.48 188.11,112.48 188.62,111.97 188.62,104.35 187.03,102.76 178.4,102.76
VPWRIN_PREFUSE on TOP: 169.32,107.65 173.76,107.65 174.27,107.14 174.27,102.57 173.51,101.81 168.94,101.81 168.3,102.44 168.3,106.63
VPWRIN_PREFUSE on BOTTOM: 165.38,107.65 172.49,107.65 173.89,106.25 173.89,102.21 173.48,101.81 165.38,101.81 164.49,102.7 164.49,106.76
VRTC_OUT on TOP (solid shape): 142.11,135.72 142.11,133.18 141.61,132.67 140.84,132.67 140.42,133.09 140.42,133.36 140.43,133.37 140.43,134.89 140.63,135.1 140.7,135.16 140.75,135.24 141.35,135.84 141.99,135.84
VRTC_OUT on BOTTOM: 91.69,101.47 91.69,104.77 106.25,119.33 109.81,119.33 113.03,122.55 119.89,122.55 122.05,124.71 122.05,137.37 126.36,141.69 138.43,141.69 141.73,138.38 141.73,134.19 141.48,133.94 140.76,133.94 139.83,134.87 139.83,136.48 138.94,137.37 135,137.37 134.37,136.73 126.24,136.73 125.48,135.97 125.48,121.92 122.05,118.49 115.32,118.49 112.6,115.78 106.43,115.78 99.95,109.3 99.95,101.55 96.31,97.92 94.49,97.92 94.36,98.04 94.36,98.81
VSDMMC on BOTTOM (solid shape): 112.14,131.7 112.14,128.27 113.66,126.75 113.66,125.06 113.66,124.75 113.66,124.74 113.66,123.7 113.28,123.32 112.27,123.32 111.89,123.7 111.89,125.98 109.73,128.14 109.73,131.83 109.98,132.08 111.76,132.08
VSDMMC on TOP: 85.09,109.09 86.87,109.09 87,108.97 87,107.7 86.87,107.57 85.09,107.57 84.84,107.82 84.84,108.84
VSDMMC on BOTTOM: 96.65,87.58 97.33,87.58 97.66,87.25 97.66,87.06 97.52,86.92 96.37,86.92 96.09,87.2 95.4,87.2 94.49,88.11 94.49,92.92 94.74,93.17 95.76,93.17 96.01,92.92 96.01,88.22
VSDMMC on BOTTOM: 86.89,149.18 87.86,149.18 88.06,148.98 88.06,146.44 88.8,145.7 92.76,145.7 93.32,146.26 93.32,149.48 93.62,149.79 94.97,149.79 95.12,149.64 95.12,144.02 95.63,143.51 97.92,143.51 100.15,141.27 100.15,139.52 98.55,137.92 97.54,137.92 97.16,138.3 95.76,138.3 90.98,143.08 88.7,143.08 86.61,145.17 86.61,148.9
VSDMMC on L4_SIG2: 84.58,109.56 85.72,109.56 86.61,108.67 86.61,103.84 95.76,94.7 95.76,91.65 94.36,90.25 92.96,90.25 90.8,92.41 90.8,94.95 90.02,95.74 85.83,95.74 82.68,98.89 82.68,107.65
VSDMMC on L10_SIG4: 92.94,92.77 95.38,92.77 95.66,92.49 95.66,90.04 95.45,89.84 94.61,89.84 94.08,90.37 92.89,90.37 92.71,90.55 92.71,92.54
VSDMMC on L10_SIG4: 109.73,132.72 111.25,132.72 111.89,132.08 111.89,130.81 111.51,130.43 110.49,130.43 109.47,131.44 109.47,132.46
VSMPS1_2 on TOP (solid shape): 154.56,133.56 154.56,127.46 153.92,126.83 151.89,126.83 151.77,126.95 151.77,134.07 152.27,134.57 153.54,134.57
VSMPS1_2 on BOTTOM (solid shape): 154.69,134.07 154.69,126.95 154.31,126.57 152.02,126.57 151.64,126.95 151.64,133.81 152.4,134.57 154.18,134.57
VSMPS1_2 on TOP: 113.16,134.6 116.31,134.6 116.71,134.19 116.71,130.76 116.15,130.21 114.83,130.21 113.03,132.01 113.03,134.47
VSMPS1_2 on L8_GND3: 153.04,126.36 152.4,125.73 148.59,125.73 142.92,131.4 138.43,131.4 130.18,123.14 112.44,123.14 111.12,124.46 111.12,133.94 112.39,135.21 129.54,135.21 137.41,143.08 149.48,143.08 153.04,139.53
VSMPS1_SW on TOP (solid shape): 151.13,134.07 151.13,132.03 149.61,130.51 149.1,130.51 147.96,129.37 147.96,129.11 146.49,127.65 144.71,127.65 144.65,127.72 144.65,128.25 144.65,128.26 144.65,128.31 144.76,128.41 144.84,128.41 145.03,128.61 145.03,130.13 147.7,132.8 147.7,134.19 147.83,134.32 150.88,134.32
VSMPS2_SW on TOP (solid shape): 151.26,128.99 151.26,126.07 151,125.81 145.16,125.81 144.7,126.28 144.7,126.87 145.03,127.21 146.69,127.21 146.96,127.49 147.04,127.52 147.12,127.48 147.73,127.43 147.69,128.04 147.65,128.12 147.68,128.2 148.34,128.86 148.34,129.11 148.59,129.37 150.88,129.37
VSMPS3 on TOP: 151.89,124.92 154.94,124.92 155.45,124.41 155.45,119.72 155.19,119.46 151.77,119.46 151.38,119.84 151.38,124.41
VSMPS3_SW on TOP (solid shape): 150.88,124.92 150.88,122.26 150.5,121.87 149.1,121.87 147.57,123.4 145.92,123.4 145.29,124.03 145.29,124.8 145.92,125.43 150.37,125.43
VSMPS4_5 on BOTTOM (solid shape): 130.56,120.83 130.56,119.06 130.3,118.8 127.51,118.8 127.13,119.18 127.13,120.96 127.25,121.09 130.3,121.09
VSMPS4_5 on BOTTOM (solid shape): 130.56,129.75 130.56,129.45 130.35,128.99 130.56,128.52 130.56,127.97 130.3,127.72 127.51,127.72 127.13,128.1 127.13,129.88 127.25,130 130.3,130
VSMPS4_5 on TOP: 120.4,130.92 121.13,131.65 121.13,134.47 121.36,134.7 124,134.7 124.31,134.4 124.31,132.16 126.59,129.88 130.3,129.88 130.43,129.75 130.43,129.62 130.56,129.49 130.56,128.1 130.3,127.84 129.92,127.84 129.79,127.72 129.67,127.84 126.75,127.84 125.09,126.19 125.09,122.38 126.36,121.11 130.3,121.11 130.81,120.6 130.81,119.21 130.43,118.83 129.54,118.83 128.02,117.3 121.79,117.3 120.4,118.7
VSMPS4_SW on TOP (solid shape): 132.06,127.96 133.24,127.96 133.6,127.59 133.6,126.18 133.22,125.8 132.06,125.8 130.79,124.53 130.5,124.53 130.18,124.69 129.85,124.53 127.24,124.53 127.19,124.58 127.19,126.73 127.67,127.21 129.92,127.21 130.68,127.97 132.05,127.97
VSMPS5_SW on TOP (solid shape): 133.27,125.36 133.27,122.96 131.67,121.37 127.38,121.37 127.08,121.66 127.08,123.89 127.27,124.07 127.32,124.07 127.32,124.08 129.83,124.08 130.18,123.88 130.52,124.08 130.73,124.08 130.81,124.15 130.95,124.15 132.2,125.4 133.22,125.4
VSMPS6_SW on TOP (solid shape): 138.05,120.6 138.05,120.39 138.03,120.37 138.03,116.14 136.91,115.02 133.99,115.02 133.57,115.43 133.57,116.4 133.6,116.42 133.6,117.44 133.73,117.73 133.6,118.02 133.6,118.56 134.11,119.08 135.1,119.08 135.1,119.08 136.81,119.08 137.67,119.94 137.67,120.68 137.82,120.83
VSMPS7 on TOP (solid shape): 130.51,135.58 130.51,133.91 130.35,133.74 126.88,133.74 126.67,133.96 126.67,135.74 127.06,136.13 129.96,136.13
VSMPS7 on BOTTOM (solid shape): 130.68,135.72 130.68,134.19 130.35,133.86 127.33,133.86 127.13,134.07 127.13,135.84 127.51,136.23 130.18,136.23
VSMPS7 on TOP: 105.79,134.7 107.52,134.7 107.65,134.57 107.65,131.7 107.34,131.4 105.92,131.4 105.54,131.78 105.54,134.45
VSMPS7 on L7_PWR2: 130.81,138.51 130.81,133.81 127.64,130.64 116.08,130.64 114.68,129.24 114.68,126.7 114.17,126.19 105.79,126.19 103.38,128.61 103.38,138.26 105.16,140.04 129.29,140.04
VSMPS7_SW on TOP (solid shape): 130.3,132.54 133.99,128.86 134.53,128.86 134.54,128.86 134.65,128.84 134.75,128.86 134.76,128.86 134.86,128.86 134.87,128.84 136.22,128.84 136.32,128.74 136.33,128.68 136.33,128.22 136.23,128.13 136.12,128.13 136.08,128.17 136.04,128.2 135.98,128.26 135.72,128.26 135.66,128.2 135.62,128.17 135.59,128.13 135.32,128.13 135.05,128.26 134.79,128.13 134.52,128.13 134.36,128.25 134.16,128.25 134.13,128.24 134.04,128.34 132.22,128.34 130.18,130.38 127.25,130.38 127.12,130.51 127.12,132.24 127.47,132.59 130.3,132.59
VSMPS8 on TOP (solid shape): outline of 127 points within 143,104.39 146.56,113.62
VSMPS8_SW on TOP (solid shape): 143,119.59 144.75,119.59 146.69,117.66 146.69,115.65 146.3,115.27 143.13,115.27 142.75,115.65 142.75,118.06 141.99,118.83 141.99,119.97 142.11,120.1 142.49,120.1
VSMPS9 on TOP (solid shape): 142.09,112.63 142.09,111.05 141.61,110.57 138.56,110.57 138.18,110.95 138.18,112.98 138.81,113.62 141.1,113.62
VSMPS9 on BOTTOM (solid shape): 140.97,125.68 140.97,124.41 140.84,124.29 138.18,124.29 138.13,124.24 138.12,124.23 138.02,124.17 137.95,124.07 137.95,124.06 137.92,124.03 137.92,123.91 137.92,123.17 137.92,123.14 136.27,123.14 136.15,123.27 136.14,123.27 136.14,125.3 136.54,125.7 139.34,125.7 139.57,125.93 140.72,125.93
VSMPS9 on L4_SIG2: 143.09,125.17 143.09,111.84 141.58,110.34 139.01,110.34 138.3,111.04 138.3,118.09 137.34,119.05 137.34,126.01 138.43,127.11 141.15,127.11
VSMPS9 on L10_SIG4: 137.67,126.32 141.22,126.32 141.61,125.94 141.61,124.41 141.35,124.16 137.67,124.16 137.54,124.29 137.54,126.19
VSMPS9_SW on TOP (solid shape): 139.57,119.84 139.57,119.3 140.43,118.44 140.97,118.44 141.1,118.32 141.86,118.32 142.11,118.06 142.11,115.52 141.73,115.14 138.68,115.14 138.43,115.4 138.43,118.83 139.19,119.59 139.19,119.84 139.32,119.97 139.45,119.97
VUSB_FTDI on TOP: 178.54,16.76 178.97,17.2 179.78,17.2 180.14,16.84 180.14,15.88 179.91,15.65 175.54,15.65 174.5,14.61 174.5,12.95 174.24,12.7 173.36,12.7 173.1,12.95 173.1,14.94 174.92,16.76
VUSB_FTDI on L8_GND3: 178.05,57.97 178.05,89.41 174.67,92.79 164.97,92.79 164.06,91.88 164.06,90.61 164.74,89.92 169.49,89.92 173.48,85.93 173.48,61.68 170.94,59.14 170.97,59.14 168.66,56.82 168.66,19.51 173.48,14.69 176.77,14.69 179.2,17.12 179.2,56.82
VUSB_JTAG on TOP: 182.12,16.9 182.3,16.72 183.15,16.72 183.36,16.51 183.36,15.49 183.01,15.14 181.27,15.14 180.64,15.77 180.64,17.93 180.88,18.17 181.89,18.17 182.12,17.94
VUSB_VBUS1 on BOTTOM: 36.32,6.35 37.29,6.35 38.43,7.49 41.12,7.49 41.58,7.04 41.58,2.21 40.77,1.4 36.45,1.4 35.81,2.03 35.81,5.84
VUSB_VBUS1 on BOTTOM: 25.27,13.34 25.27,10.29 25.53,10.03 29.21,10.03 29.59,10.41 29.59,13.08 28.83,13.84 25.78,13.84
VUSB_VBUS1 on L10_SIG4: 28.21,18.8 35.31,18.8 41.27,12.83 41.27,4.57 38.81,2.11 31.35,2.11 25.35,8.11 25.35,15.93
VUSB_VBUS2 on TOP: 8.94,34.24 8.13,35.05 8.13,40 7.21,40.92 6.73,40.92 6.73,41.36 7.11,41.74 8.38,41.74 8.64,41.48 8.64,40.98 9.02,40.59 10.46,40.59 11.56,39.5 16.72,39.5 17.78,38.44 19.56,38.44 19.81,38.69 19.81,40.59 20.07,40.85 24.4,40.85 26.09,39.17 26.09,37.92 22.41,34.24
VUSB_VBUS2 on BOTTOM: 3.43,39.96 9.78,39.96 10.03,39.71 10.03,37.67 9.78,37.42 8.51,37.42 7.24,38.69 5.84,38.69 4.95,39.58 3.43,39.58
N11220684 on TOP: 108.8,15.81 109.9,15.81 110.27,15.44 110.27,13.58 110.38,13.47 110.89,13.47 110.98,13.56 110.98,16.6 110.76,16.81 108.97,16.81 108.77,16.61 108.77,15.84
N12225158 on L3_SIG1 (solid shape): outline of 349 points within 24.21,95.59 33.91,100.54
N16839102 on TOP: 187.17,79.39 187.35,79.2 188.14,79.2 188.43,78.91 188.43,77.85 188.18,77.6 184.79,77.6 184.66,77.72 184.66,80.5 184.99,80.83 186.98,80.83 187.17,80.65
N16839102 on BOTTOM: 187.2,80.64 187.2,78.59 186.42,77.81 185.93,77.81 185.93,79.63 185.55,79.63 185.19,79.98 185.19,80.64 185.37,80.82 187.03,80.82
N17594977 on L3_SIG1 (solid shape): outline of 608 points within 24.21,77.75 35.64,83.16
N17596823 on L3_SIG1 (solid shape): outline of 600 points within 24.21,53.5 35.64,58.76
N19923823 on BOTTOM: 110.03,92.54 110.9,92.54 111.12,92.31 111.12,91.74 110.85,91.47 110.08,91.47 109.86,91.69 109.86,92.36
N19923823 on L4_SIG2: 107.21,86.16 109.5,86.16 110.11,86.77 110.11,93.17 110.36,93.43 111.25,93.43 111.48,93.2 111.48,85.63 110.19,84.33 107.11,84.33 106.71,84.74 106.71,85.65
N19923823 on L10_SIG4: 109.92,91.33 109.92,93.11 110.17,93.36 110.68,93.36 110.81,93.24 110.81,91.46 110.55,91.2 110.05,91.2
N19923824 on L4_SIG2: 107.34,86.42 108.86,86.42 109.65,87.2 109.65,92.74 109.22,93.17 108.58,93.17 108.18,92.77 108.18,87.56 107.75,87.13 107.47,87.13 107.21,86.87 107.21,86.54
N19923824 on L10_SIG4: 108.39,91.08 108.39,92.85 108.65,93.11 109.16,93.11 109.28,92.98 109.28,91.2 109.03,90.95 108.52,90.95
N19923831 on BOTTOM: 118.67,78.16 118.67,76.94 118.44,76.71 117.98,76.71 117.73,76.97 117.73,78.16 117.93,78.36 118.47,78.36
N19923831 on L5_GND2: 106.63,77.86 119.13,77.86 119.43,77.55 119.43,77.12 119.2,76.89 113.49,76.89 112.98,76.38 111.61,76.38 111.1,76.89 106.6,76.89 106.38,77.12 106.38,77.6
N19923831 on L10_SIG4: 118.11,78.44 119.38,78.44 119.76,78.06 119.76,77.45 119.28,76.97 118.44,76.97 117.98,77.42 117.98,78.31
N19923833 on L4_SIG2: 106.4,86.47 106.91,86.47 107.29,86.85 107.29,87.05 107.59,87.36 107.62,87.36 107.62,92.61 107.06,93.17 106.55,93.17 106.3,92.92 106.3,89.24 105.61,88.55 105.61,87.51 106.3,86.82 106.3,86.57
N19923833 on L10_SIG4: 106.17,91.01 106.17,92.79 106.43,93.05 106.93,93.05 107.06,92.92 107.06,91.14 106.81,90.89 106.3,90.89
N19923834 on BOTTOM: 114.64,73.74 115.06,73.74 115.37,73.44 115.37,72.44 115.19,72.26 114.68,72.26 114.43,72.52 114.43,73.53
N19923834 on L7_PWR2: 107.21,77.7 108.08,77.7 108.74,77.04 113.39,77.04 115.09,75.34 115.09,74.05 114.78,73.74 114.33,73.74 112.48,75.59 107.26,75.59 107.04,75.82 107.04,77.53
N19923834 on L10_SIG4: 114.15,74.99 115.09,74.99 115.7,74.38 115.7,72.77 115.19,72.26 114.55,72.26 113.94,72.87 113.94,74.78
N19923844 on L4_SIG2: 106.05,86.57 106.05,86.67 105.54,87.18 105.54,91.78 104.39,92.92 103.89,92.92 103.61,92.64 103.61,86.26 103.89,85.98 105.46,85.98
N19923844 on L10_SIG4: 103.76,92.54 104.14,92.92 104.52,92.92 104.9,92.54 104.9,91.27 104.52,90.89 104.27,90.89 103.76,91.39
N19923853 on L10_SIG4: 103.12,76.28 103.12,70.06 101.85,68.79 100.97,68.79 99.19,70.57 99.19,76.66 99.69,77.17 102.23,77.17
N20127658 on BOTTOM: 81.28,86.87 82.17,86.87 82.42,86.61 82.42,85.17 82.25,84.99 81.2,84.99 81.1,85.09 81.1,86.69
N20127658 on L9_SIG3: 84.96,80.52 91.31,80.52 91.82,81.03 91.82,82.17 87.25,86.74 82.93,86.74 82.42,86.23 82.42,83.06
N20127658 on L10_SIG4: 88.39,83.14 90.17,83.14 90.68,82.63 90.68,82.12 90.42,81.87 89.86,81.87 89.61,82.12 88.27,82.12 88.01,82.38 88.01,82.76
N20127658 on L10_SIG4: 82.17,86.87 83.26,86.87 83.72,86.41 83.72,85.7 82.98,84.96 82.04,84.96 81.79,85.22 81.79,86.49
N20128389 on BOTTOM: 95.76,83.06 96.01,83.06 96.14,83.19 96.14,83.44 95.25,84.33 92.84,84.33 92.33,84.84 92.33,86.11 94.11,87.88 94.11,95.25 95.5,96.65 95.5,97.28 95.25,97.54 91.82,97.54 91.57,97.28 91.57,93.09 92.79,91.87 92.79,88.21 91.44,86.87 91.44,83.82 91.95,83.31 95.5,83.31
N20287584 on TOP: 159.38,123.91 159.13,124.15 159.13,125.56 159.51,125.94 159.51,134.07 159.64,134.19 160.66,134.19 161.67,133.18 161.67,129.11 161.42,128.86 161.42,124.09 161.24,123.91
N20619479 on BOTTOM: 70.74,113.24 70.74,114 70.87,114.13 72.9,114.13 73.15,114.38 73.91,114.38 74.04,114.25 74.04,113.11 73.91,112.98 73.28,112.98 73.15,113.11 70.87,113.11
N20664562 on BOTTOM (solid shape): 152.15,113.25 152.45,113.01 152.82,113.12 152.89,113.15 152.96,113.12 153.47,112.62 153.47,109.7 154.67,108.49 154.67,107.6 154.9,107.37 154.91,107.31 154.87,107.28 154.74,107.28 153.85,108.17 153.5,108.17 153.48,108.19 152.82,108.19 151.05,109.95 151.05,112.87 151.43,113.25
N20665027 on BOTTOM (solid shape): 159.05,112.87 159.05,110.35 155.99,107.28 155.82,107.28 155.72,107.34 155.74,107.45 155.79,107.51 155.82,107.57 155.91,107.65 155.91,108.69 155.63,108.97 155.63,112.87 156.13,113.38 158.55,113.38
N21605448 on TOP: 15.88,39.88 16.26,40.26 16.26,46.74 15.75,47.24 13.97,47.24 13.34,46.61 13.34,43.43 12.45,42.55 12.45,40.51 13.08,39.88
N21685968 on BOTTOM: 118.75,82.38 119.76,82.38 120.14,82 120.14,80.6 119.89,80.35 119.33,80.35 119,80.67 118.67,80.67 118.36,80.98 118.36,82
N21685968 on L7_PWR2: 106.55,83.14 118.24,83.14 118.62,82.76 118.62,82 118.36,81.74 106.55,81.74 106.3,82 106.3,82.89
N21685968 on L10_SIG4: 116.71,81.62 118.11,81.62 118.36,81.36 118.36,80.98 118.62,80.73 119.51,80.73 119.76,80.98 119.76,82.63 119.51,82.89 116.71,82.89 116.46,82.63 116.46,81.87
N23040939 on BOTTOM (solid shape): 38.35,96.39 38.35,94.36 38.1,94.11 35.81,94.11 35.64,94.28 35.64,96.34 35.81,96.52 36.32,96.52 38.23,96.52
N23040957 on BOTTOM (solid shape): 35.25,96.44 35.25,94.13 35.31,94.08 35.31,93.98 36.2,93.09 38.1,93.09 38.23,92.96 38.23,92.33 37.97,92.08 37.97,91.57 37.97,91.06 37.72,90.8 36.96,90.8 34.42,93.34 34.42,96.27 34.67,96.52 35.18,96.52
N23041291 on BOTTOM (solid shape): 116.46,127.51 116.46,125.22 116.28,125.04 114.22,125.04 114.05,125.22 114.05,125.73 114.05,127.64 114.17,127.76 116.2,127.76
N23041299 on BOTTOM (solid shape): outline of 233 points within 114.05,122.94 119.76,127.64

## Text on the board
BOTTOM: PN#: 3M0000 | LAYER 12 SECONDARY SIDE | 12
Ref Des/Silkscreen Bottom: A1 | 1 | 2 | 7 | A | 8 | 12 | 9 | 14 | 4 | 5 | C | B | 60 | 3 | 59 | 29 | 24 | 23 | 30 | +
User.Comments: CR_UNNAMED_4
TOP: LAYER 1 - PRIMARY SIDE | 1 | 12
Ref Des/Silkscreen Top: 2 | 1 | 5 | 3 | 4 | 29 | 30 | 24 | 23 | 7 | 8 | 5.0VDC | 4.0A | GND | PRU2 ETH1 | PRU2 ETH0 | PRU1ETH1 | PRU1ETH0 | Gb Ethernet0 | USB1 | Gb Ethernet1 | VDDS_DDR1 | HDMI | Profibus | VDD | VDD_MPU | VDD_IVA | Expansion Connector | CAN | Power On | Hard | RS-485 | Reset | Warm | 8A Slow Blow | 125VAC, 125VDC | VMAIN | CAMERA | JTAG | INDUSTRIAL LED0 | INDUSTRIAL LED1 | INDUSTRIAL LED2 | INDUSTRIAL LED3 | STATUS LED1 | STATUS LED0 | Industrial I/O | USB JTAG | Catalog Processors | AM571x Industrial EVM | REV 1.3A | ASSM PN#:4P0052 | SN#:__________ | PCIE | SD/MMC1
PAGE_OUTLINE: TI
DISPLAY_BOTTOM: SILKSCREEN TOP | 1 | 2
DIMENSION: 2 | ASSEMBLY BOTTOM
BODY_CENTER: ASSEMBLY TOP | 1 | 2
DEVICE_TYPE_TOP: FABRICATION DRAWING | 1
User.8: LAYER 2 - GROUND LAYER 1 | 2 | 12
User.9: LAYER 3 - SIGNAL LAYER 1 | 3 | 12
User.10: LAYER 4 - SIGNAL LAYER 2 | 4 | 12
User.11: LAYER 5 - GROUND LAYER 2 | 5 | 12
User.12: SOLDER MASK BOTTOM | 2
User.13: SOLDER MASK TOP | 1 | 2
User.14: SOLDER PASTE BOTTOM | 2
User.15: SOLDER PASTE TOP | 1 | 2
User.16: SILKSCREEN BOTTOM | 2
User.18: LAYER 6 - POWER LAYER 1 | 6 | 12
User.19: LAYER 7 -POWER LAYER 2 | 7 | 12
User.20: ACTIVE AREA CENTER | LCD CONNECTOR LOCATION | LCD AND TS TOP VIEW
User.23: LAYER 8 - GROUND LAYER 3 | 8 | 12
User.24: LAYER 9 - SIGNAL LAYER 3 | 9 | 12
User.25: LAYER 10 - SIGNAL LAYER 4 | 10 | 12
User.26: LAYER 11 - GROUND LAYER 4 | 11 | 12
User.27: BOARD NAME: | BOARD NO: 3M0000 | CUSTOMER NAME: | AM571X_INDUSTRIAL_EVM | TEXAS INSTRUMENTS | REV: 1.3A | DESCRIPTION: | DATE: 12/31/2015 | SH | OF
User.28: OF | SH | DATE:12/31/2015 | DESCRIPTION: | TEXAS INSTRUMENTS | REV:1.3A | AM571X_INDUSTRIAL_EVM | BOARD NAME: | CUSTOMER NAME: | BOARD NO:3M0000
User.29: L9_SIG3 | L1_TOP | L3_SIG1 | L4_SIG2 | L10_SIG4 | L12_BOTTOM | LAYERS | in mils | TRACE | WIDTH | 4.3 | 4.5 | 6.8 | +/-10% | TARGET | SINGLE-ENDED | Ohms | 50 | 4.2 | - | 60 | 5.9 | EDGE-COUPLED DIFFERENTIAL | SPACE | 7.7 | 6.1 | 90 | 3.25 | 4.25 | 3.9 | 8.75 | 8.1 | 5.75 | 100
